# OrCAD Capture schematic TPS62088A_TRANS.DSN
size D
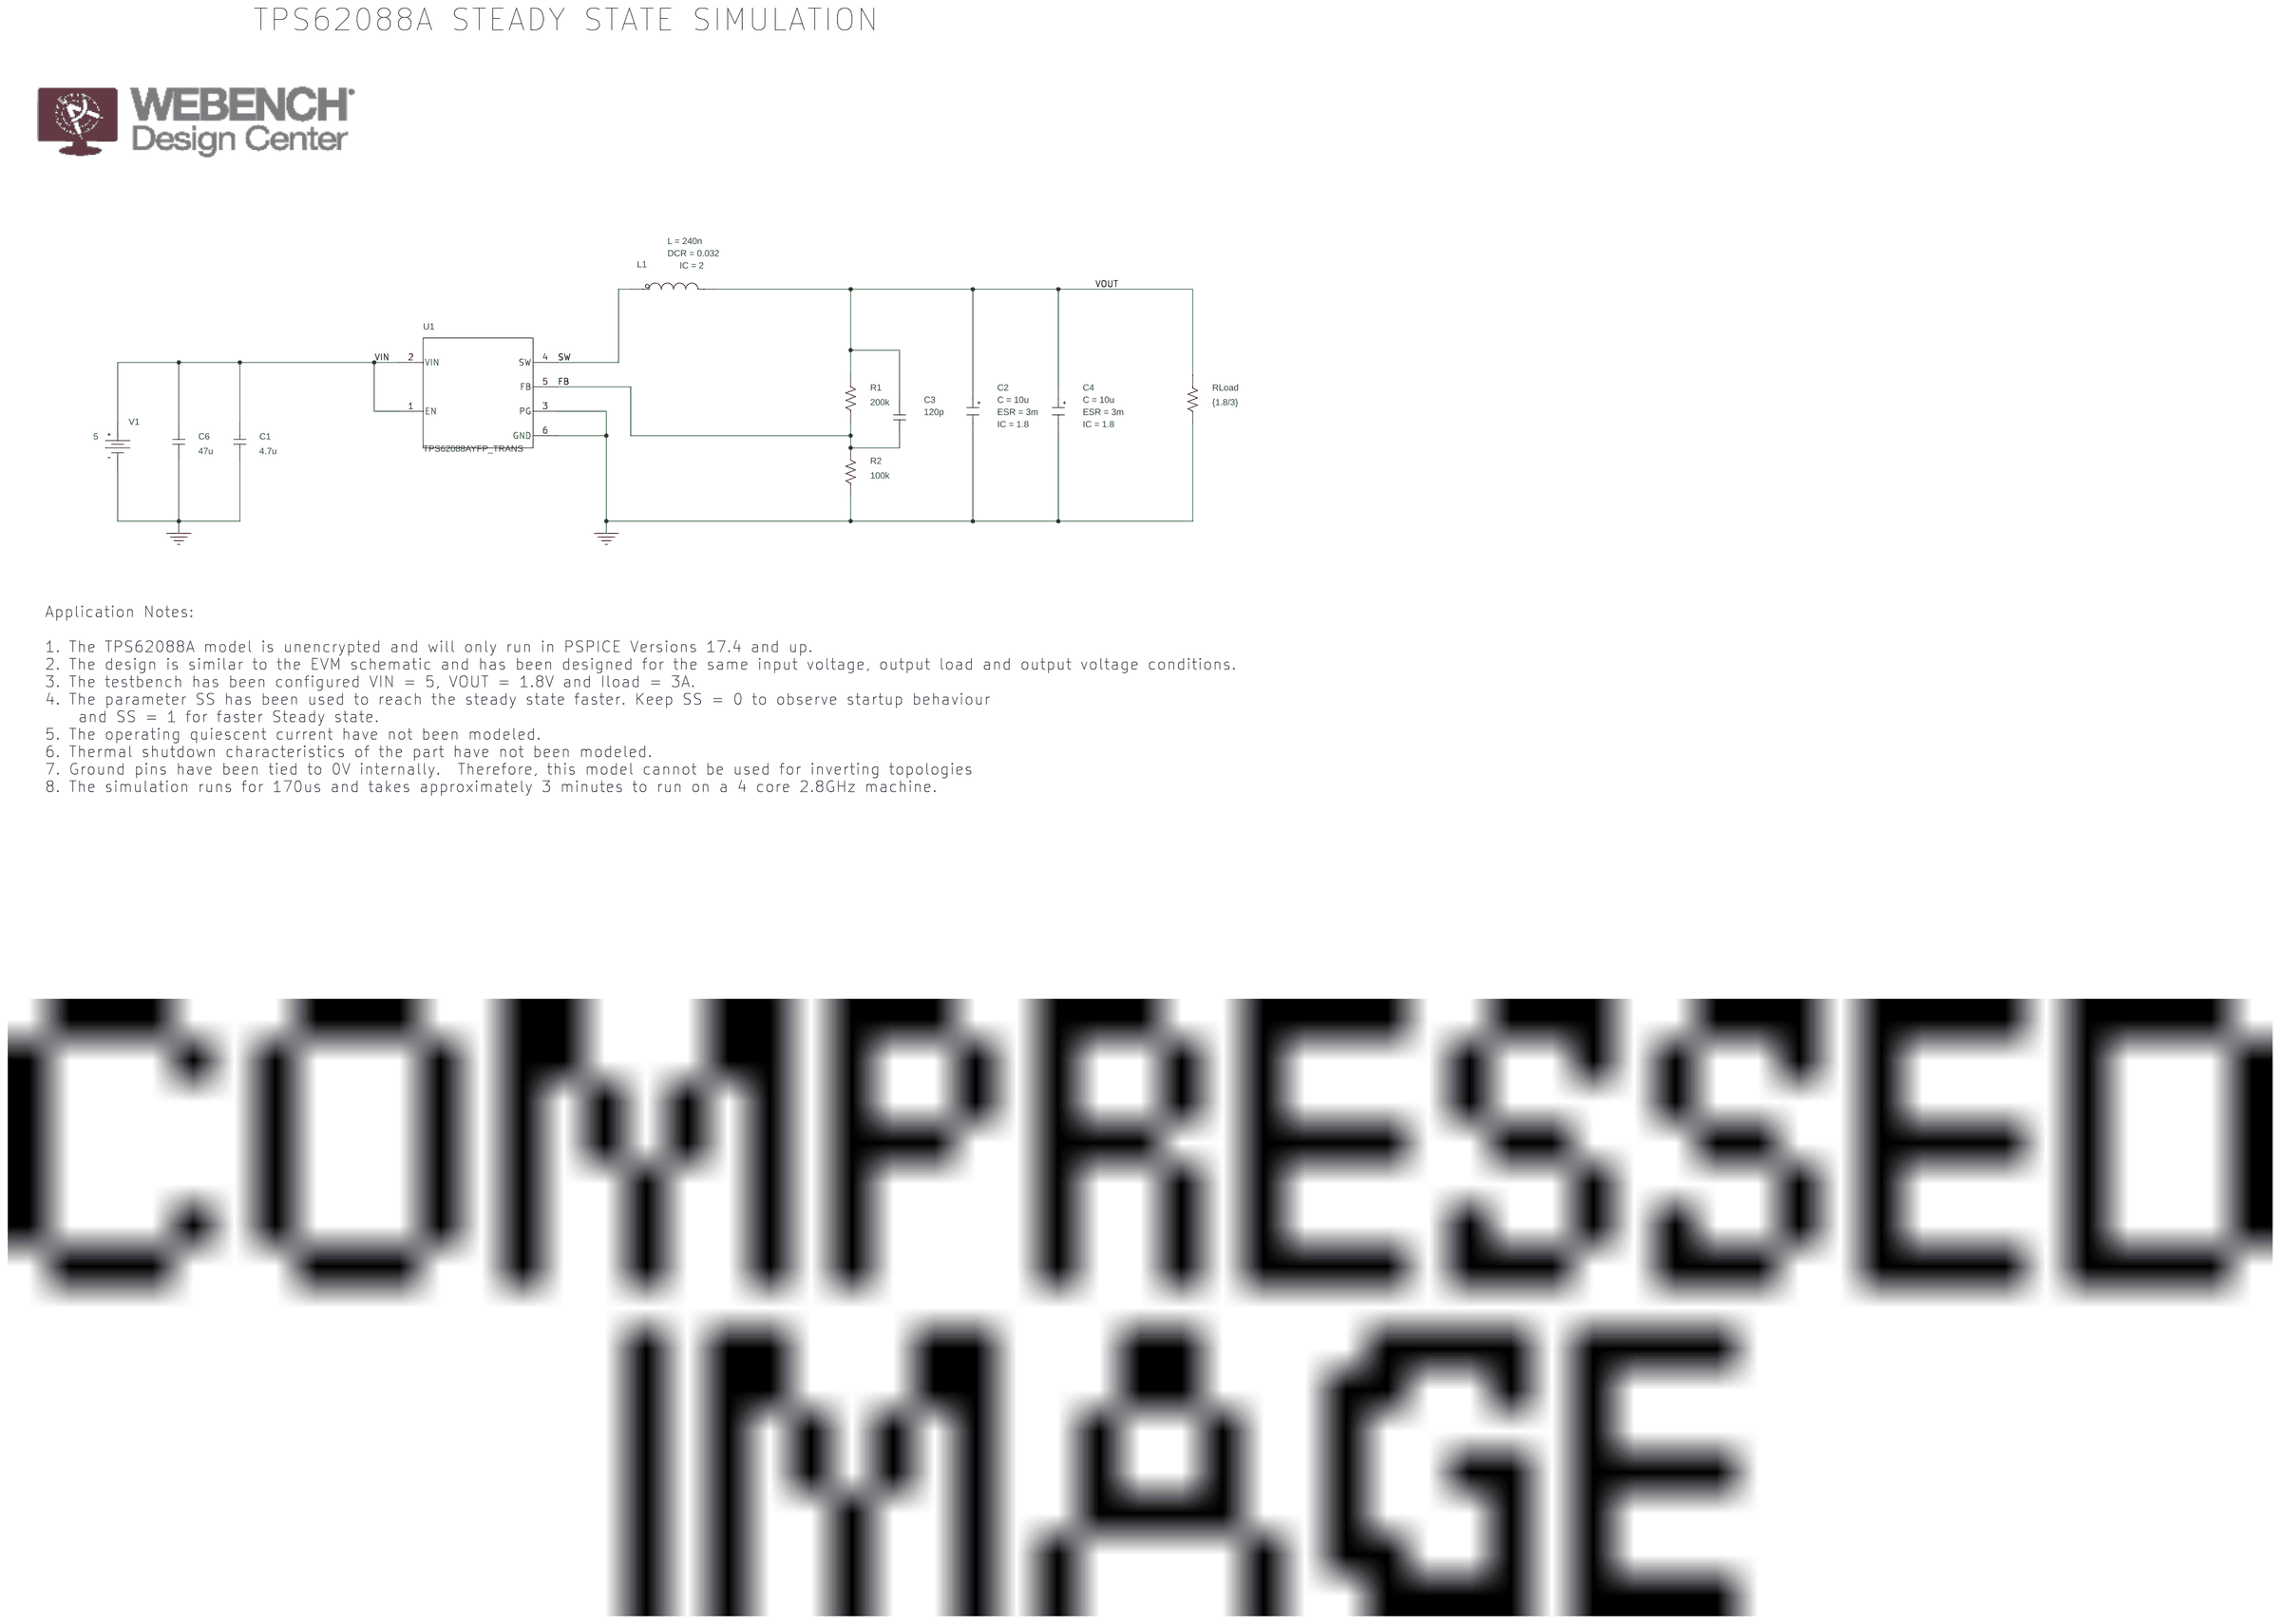
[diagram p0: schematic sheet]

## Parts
C1  4.7u  [RAD/CK05]
C2  CESR
C3  120p  [RAD/CK05]
C4  CESR
C6  47u  [RAD/CK05]
L1  LDCR
R1  200k  [AX/RC05]
R2  100k  [AX/RC05]
RLoad  {1.8/3}  [AX/RC05]
U1  TPS62088AYFP_TRANS  [YFP0006-C01-IPC_]
V1  VDC

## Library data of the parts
C1 C6 = C: IC: 0
C2 C4 = CESR_0: C: 10u; ESR: 3m; IC: 1.8; PSpiceTemplate: X^@REFDES %IN %OUT @MODEL PARAMS:  ?C|C=@C||C=100u|  ?ESR|ESR=@ESR||ESR=0.01| ?X|X=@X||X=2|  ?IC|IC=@IC||IC=2|; X: 1
C3 = C
L1 = LDCR_0: DCR: 0.032; IC: 2; L: 240n; PSpiceTemplate: X^@REFDES %IN %OUT @MODEL PARAMS:  ?L|L=@L||L=1u|  ?DCR|DCR=@DCR||DCR=0.01| ?IC|IC=@IC||IC=0|
R1 R2 RLoad = R
U1 = TPS62088AYFP_TRANS
V1 = VDC: DC: 5

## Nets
VIN: C1.1 C6.1 U1.1(EN) U1.2(VIN) V1.0(+)
0: C1.2 C2.3(OUT) C4.3(OUT) C6.2 R2.1 RLoad.2 U1.3(PG) U1.6(GND) V1.1(-)
FB: C3.2 R1.1 R2.2 U1.5(FB)
SW: L1.1(IN) U1.4(SW)
VOUT: C2.1(IN) C3.1 C4.1(IN) L1.3(OUT) R1.2 RLoad.1

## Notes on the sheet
- TPS62088A STEADY STATE SIMULATION
- Application Notes:
  1. The TPS62088A model is unencrypted and will only run in PSPICE Versions 17.4 and up.
  2. The design is similar to the EVM schematic and has been designed for the same input voltage, output load and output voltage conditions.
  3. The testbench has been configured VIN = 5, VOUT = 1.8V and Iload = 3A.
  4. The parameter SS has been used to reach the steady state faster. Keep SS = 0 to observe startup behaviour
      and SS = 1 for faster Steady state.
  5. The operating quiescent current have not been modeled.
  6. Thermal shutdown characteristics of the part have not been modeled.
  7. Ground pins have been tied to 0V internally.  Therefore, this model cannot be used for inverting topologies
  8. The simulation runs for 170us and takes approximately 3 minutes to run on a 4 core 2.8GHz machine.
